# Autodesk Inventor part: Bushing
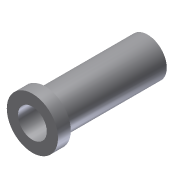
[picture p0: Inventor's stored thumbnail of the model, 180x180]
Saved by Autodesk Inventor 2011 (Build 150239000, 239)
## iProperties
Shininess: 77.0
Length Units: 11269
Angle Units: 11279
Time Units: 11290
Mass Units: 11283
Length Display Precision: 3
Angle Display Precision: 2
Created: 2002-02
Part Number: Bushing
Document SubType Name: Modeling
Designer: ***
Density: 1 g/cm^3
Density: 0.0
Volumn: 0.0
Area: 0.0
PropertySet Name: Model Information
Control State: 0
Master: False
Checked Out: False
Author: ***
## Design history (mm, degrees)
sketch "Sketch1"
  geometry: L1 (6.25, 50.44)-(6.25, 5.44); L2 (6.25, 5.44)-(10.625, 5.44); L3 (10.625, 5.44)-(10.625, 10.44); L4 (10.625, 10.44)-(8.125, 10.44); L5 (8.125, 10.44)-(8.125, 50.44); L6 (8.125, 50.44)-(6.25, 50.44); L7 (0.625, 34.884)-(0.625, 0)
  constraints: 14 end point, 4 parallel, 2 perpendicular, 1 vertical
  dimensions: "d0" = 20 diameter of L3 L7; "d1" = 11.25 diameter of L1 L7; "d2" = 15 diameter of L5 L7; "d4" = 5 distance of L2.end L3.end; "d5" = 45 distance of L1.start L1.end
revolve "Revolution1" sketch "Sketch1" stored, may be unused: angle "d3" = 90 deg
body "Solid1"
